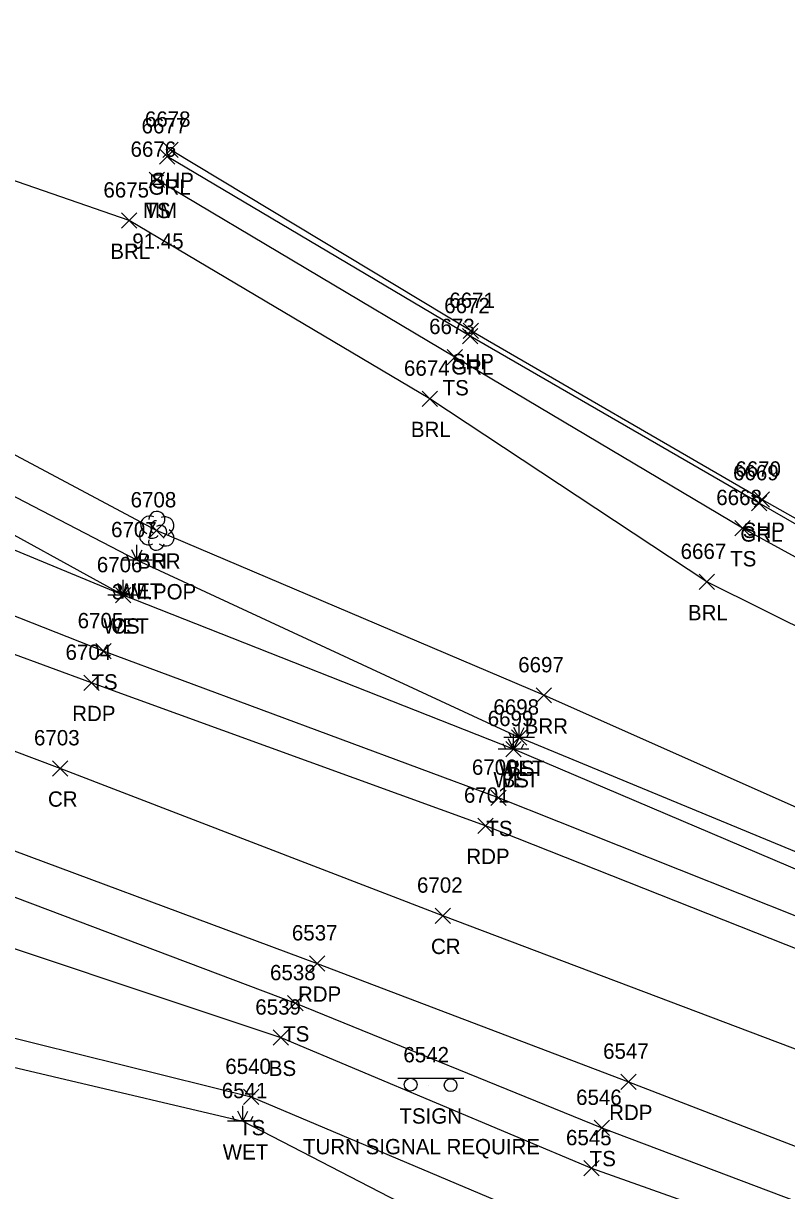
# Model space of a CAD drawing. Extents: x 1462089 to 1464015, y 730534 to 736144.
# Drawn here: x 1462817.1 to 1462916.7, y 731511.1 to 731663.4 of the extents above; entities that cross this region are included whole.
import ezdxf

# ---------------------------------------------------------------- set-up
doc = ezdxf.new("R2010")
doc.units = 0
for name, color, linetype in [('L_A', 7, 'Continuous'), ('L_C', 7, 'Continuous'), ('L_I', 7, 'Continuous'), ('L_TIC', 7, 'Continuous'), ('LABL', 7, 'Continuous'), ('LELB', 7, 'Continuous'), ('LTD', 7, 'Continuous'), ('LWET', 7, 'Continuous'), ('P_A', 7, 'Continuous'), ('P_I', 7, 'Continuous'), ('P_TIC', 7, 'Continuous'), ('PET', 7, 'Continuous'), ('PRC', 7, 'Continuous'), ('PSP', 7, 'Continuous'), ('R_A', 7, 'Continuous'), ('R_I', 7, 'Continuous'), ('R_TIC', 7, 'Continuous'), ('RGR', 7, 'Continuous'), ('S_A', 7, 'Continuous'), ('S_C', 7, 'Continuous'), ('S_I', 7, 'Continuous'), ('SRM', 7, 'Continuous'), ('SSGN', 7, 'Continuous')]:
    doc.layers.add(name, color=color, linetype=linetype)

msp = doc.modelspace()

# ---------------------------------------------------------------- linework, layer by layer
at = {"layer": 'L_TIC'}
for points in [[(1462833.53, 731641.96), (1462835.53, 731643.96)], [(1462835.53, 731641.96), (1462833.53, 731643.96)], [(1462829.94, 731636.64), (1462831.94, 731638.64)], [(1462831.94, 731636.64), (1462829.94, 731638.64)], [(1462872.41, 731618.83), (1462874.41, 731620.83)], [(1462874.41, 731618.83), (1462872.41, 731620.83)], [(1462869.14, 731613.39), (1462871.14, 731615.39)], [(1462871.14, 731613.39), (1462869.14, 731615.39)], [(1462833.51, 731596.22), (1462835.51, 731598.22)], [(1462835.51, 731596.22), (1462833.51, 731598.22)], [(1462909.91, 731596.52), (1462911.91, 731598.52)], [(1462911.91, 731596.52), (1462909.91, 731598.52)], [(1462905.26, 731589.49), (1462907.26, 731591.49)], [(1462907.26, 731589.49), (1462905.26, 731591.49)], [(1462829.16, 731587.75), (1462831.16, 731589.75)], [(1462831.16, 731587.75), (1462829.16, 731589.75)], [(1462826.61, 731580.45), (1462828.61, 731582.45)], [(1462828.61, 731580.45), (1462826.61, 731582.45)], [(1462884.04, 731574.7), (1462886.04, 731576.7)], [(1462886.04, 731574.7), (1462884.04, 731576.7)], [(1462880.79, 731569.18), (1462882.79, 731571.18)], [(1462882.79, 731569.18), (1462880.79, 731571.18)], [(1462880.06, 731567.69), (1462882.06, 731569.69)], [(1462882.06, 731567.69), (1462880.06, 731569.69)], [(1462878.11, 731561.33), (1462880.11, 731563.33)], [(1462880.11, 731561.33), (1462878.11, 731563.33)], [(1462851.61, 731534.53), (1462853.61, 731536.53)], [(1462853.61, 731534.53), (1462851.61, 731536.53)], [(1462849.71, 731530.04), (1462851.71, 731532.04)], [(1462851.71, 731530.04), (1462849.71, 731532.04)], [(1462845.87, 731522.3), (1462847.87, 731524.3)], [(1462847.87, 731522.3), (1462845.87, 731524.3)], [(1462891.59, 731518.26), (1462893.59, 731520.26)], [(1462893.59, 731518.26), (1462891.59, 731520.26)], [(1462890.22, 731513), (1462892.22, 731515)], [(1462892.22, 731513), (1462890.22, 731515)]]:
    msp.add_lwpolyline(points, dxfattribs=at)
at = {"layer": 'LABL'}
for points in [[(1463031.85, 731524.15), (1463024.22, 731515.5), (1462977.15, 731533.67), (1462930.95, 731555.28), (1462885.04, 731575.7), (1462834.51, 731597.22), (1462803.07, 731613.94), (1462803.87, 731628.84), (1462811.96, 731644.23)], [(1463031.85, 731524.15), (1462988.28, 731548.09), (1462943.29, 731572.1), (1462906.26, 731590.49), (1462870.14, 731614.39), (1462830.94, 731637.64), (1462811.96, 731644.23)]]:
    msp.add_lwpolyline(points, dxfattribs=at)
at = {"layer": 'LELB'}
for points in [[(1463119.6, 731469.74), (1463069.73, 731487.53), (1463021.46, 731507.93), (1462974.33, 731526.26), (1462926.32, 731543.54), (1462879.11, 731562.33), (1462827.61, 731581.45), (1462784.13, 731598.58), (1462763.62, 731605.93), (1462736.08, 731619.36), (1462729.89, 731630.52), (1462727.38, 731651.69), (1462726.82, 731663.37)], [(1462830.16, 731588.75), (1462785.28, 731607.33), (1462764.16, 731612.54), (1462740.16, 731624.2), (1462735.77, 731624.99), (1462735.73, 731638.84), (1462738.32, 731647.97)], [(1463216.41, 731432.84), (1463196.86, 731441.6), (1463172.22, 731454.72), (1463127.76, 731480.4), (1463076.47, 731505.5), (1463033.85, 731528.54), (1462991.5, 731551.77), (1462947.03, 731577.76), (1462910.91, 731597.52), (1462873.41, 731619.83), (1462834.53, 731642.96)], [(1462725.83, 731477.73), (1462699.03, 731484.88), (1462678.02, 731490.51), (1462672.21, 731492.87), (1462685.03, 731534.1), (1462694.09, 731551.02), (1462707.07, 731562.68), (1462723.7, 731570.83), (1462738.52, 731573.85), (1462757.84, 731571.09), (1462803.89, 731553.92), (1462852.61, 731535.53), (1462892.59, 731519.26), (1462943.53, 731500), (1462989.56, 731482.33), (1463038.41, 731464.73), (1463096.36, 731442.72), (1463144.39, 731425.15), (1463184.91, 731409.31), (1463228.27, 731391.66), (1463272.85, 731369.67), (1463317.31, 731351.5), (1463360.65, 731325.78), (1463401.48, 731298.99)], [(1463198.61, 731435.81), (1463172.21, 731447.97), (1463121.62, 731472.24), (1463071.4, 731492.14), (1463023.17, 731512.08), (1462976.42, 731531.07), (1462930.04, 731550.24), (1462881.79, 731570.18)], [(1463172.21, 731447.97), (1463119.6, 731469.74), (1463070.36, 731489.69), (1463021.92, 731509.58), (1462975.42, 731528.81), (1462928.9, 731548.31), (1462881.06, 731568.69)], [(1462704.46, 731497.81), (1462686.16, 731500.02), (1462698.22, 731528.94), (1462703.29, 731542), (1462714.64, 731556.34), (1462732.86, 731563.96), (1462758.79, 731560.72), (1462800.62, 731547.77), (1462850.71, 731531.04), (1462891.22, 731514), (1462941.79, 731496.05), (1462986.9, 731476.74), (1463039.19, 731460.33), (1463094.46, 731438.38), (1463142.72, 731421.22), (1463180.95, 731402.04), (1463225.03, 731385.65), (1463269.42, 731363.58), (1463313.96, 731345.04), (1463357.55, 731320.57), (1463397.02, 731291.85), (1463445.25, 731256.26)], [(1462729.89, 731554.83), (1462752.88, 731550.71), (1462796.34, 731535.84), (1462846.87, 731523.3), (1462891.6, 731504.38), (1462938.92, 731483.15), (1462981.55, 731463.36), (1463030.83, 731437.13), (1463081.03, 731412.21)]]:
    msp.add_lwpolyline(points, dxfattribs=at)
at = {"layer": 'LTD'}
msp.add_line((1462834.51, 731597.22), (1462834.51, 731597.22), dxfattribs=at)
msp.add_line((1462834.51, 731597.22), (1462834.51, 731597.22), dxfattribs=at)
msp.add_arc((1462834.56, 731598.65), 1.05, 335.5272, 180.9563, dxfattribs=at)
for centre, major_axis, ratio, start_param, end_param in [((1462833.72, 731597.89), (1.21, -0.51), 0.895232, 1.570796, 4.712389), ((1462834.3, 731597.68), (-0.208, -0.792), 0.645439, 3.141593, 6.283185), ((1462835.01, 731597.05), (-0.5, 0.667), 0.989748, 3.141593, 6.283185), ((1462835.55, 731597.8), (-1.14, -0.48), 0.949671, 1.570796, 4.712389), ((1462833.43, 731596.51), (0.58, -1.04), 0.959034, 3.141593, 6.283185), ((1462834.05, 731596.47), (-0.625, -0.083), 0.423636, 0, 3.141593), ((1462835.51, 731596.39), (-1.09, 0.79), 0.841452, 1.570796, 4.712389), ((1462834.51, 731595.72), (0.26, 1.06), 0.942809, 1.570796, 4.712389)]:
    msp.add_ellipse(centre, major_axis=major_axis, ratio=ratio, start_param=start_param, end_param=end_param, dxfattribs=at)
at = {"layer": 'LWET'}
for p, q in [((1462831.96, 731593.33), (1462831.96, 731595.33)), ((1462833.96, 731593.33), (1462829.96, 731593.33)), ((1462830.96, 731593.33), (1462830.63, 731594)), ((1462831.96, 731593.33), (1462831.3, 731594.67)), ((1462831.96, 731593.33), (1462832.63, 731594.67)), ((1462832.96, 731593.33), (1462833.3, 731594)), ((1462830.16, 731588.75), (1462830.16, 731590.75)), ((1462832.16, 731588.75), (1462828.16, 731588.75)), ((1462829.16, 731588.75), (1462828.82, 731589.42)), ((1462830.16, 731588.75), (1462829.49, 731590.08)), ((1462830.16, 731588.75), (1462830.82, 731590.08)), ((1462831.16, 731588.75), (1462831.49, 731589.42)), ((1462881.79, 731570.18), (1462881.79, 731572.18)), ((1462881.79, 731570.18), (1462881.79, 731572.18)), ((1462880.79, 731570.18), (1462880.46, 731570.84)), ((1462880.79, 731570.18), (1462880.46, 731570.84)), ((1462881.06, 731568.69), (1462881.06, 731570.69)), ((1462881.79, 731570.18), (1462881.12, 731571.51)), ((1462881.79, 731570.18), (1462881.12, 731571.51)), ((1462881.79, 731570.18), (1462882.46, 731571.51)), ((1462881.79, 731570.18), (1462882.46, 731571.51)), ((1462882.79, 731570.18), (1462883.12, 731570.84)), ((1462882.79, 731570.18), (1462883.12, 731570.84)), ((1462880.06, 731568.69), (1462879.73, 731569.36)), ((1462883.79, 731570.18), (1462879.79, 731570.18)), ((1462883.79, 731570.18), (1462879.79, 731570.18)), ((1462881.06, 731568.69), (1462880.4, 731570.03)), ((1462881.06, 731568.69), (1462881.73, 731570.03)), ((1462882.06, 731568.69), (1462882.4, 731569.36)), ((1462883.06, 731568.69), (1462879.06, 731568.69)), ((1462845.76, 731520.14), (1462845.76, 731522.14)), ((1462844.76, 731520.14), (1462844.43, 731520.81)), ((1462845.76, 731520.14), (1462845.09, 731521.47)), ((1462845.76, 731520.14), (1462846.43, 731521.47)), ((1462846.76, 731520.14), (1462847.09, 731520.81)), ((1462847.76, 731520.14), (1462843.76, 731520.14))]:
    msp.add_line(p, q, dxfattribs=at)
for points in [[(1462881.79, 731570.18), (1462881.06, 731568.69), (1462830.16, 731588.75), (1462789.68, 731611.04), (1462784.3, 731613.31), (1462766.07, 731617.11), (1462744.21, 731627.09), (1462743.62, 731628.48), (1462744.64, 731630.73)], [(1462881.79, 731570.18), (1462831.96, 731593.33), (1462790.37, 731614.89), (1462784.14, 731617.31), (1462766.81, 731621.51), (1462744.64, 731630.73)], [(1462733.57, 731494.55), (1462725.26, 731500.55), (1462719.94, 731502.96), (1462723.6, 731512.41), (1462733.75, 731518.35), (1462743.36, 731523.25), (1462753.89, 731528.6), (1462746.86, 731535.71), (1462735.45, 731540.19), (1462722.91, 731541.96), (1462719.94, 731549.27), (1462730.7, 731550.95), (1462750.36, 731546.11), (1462796.24, 731531.79), (1462845.76, 731520.14), (1462890.22, 731497.14), (1462935.58, 731479.91), (1462979.84, 731458.59), (1463028.53, 731430.07), (1463078.39, 731408.92), (1463133.15, 731393.57), (1463171.56, 731375.44), (1463214.42, 731357.49), (1463259.4, 731337.33)]]:
    msp.add_lwpolyline(points, dxfattribs=at)
at = {"layer": 'P_TIC'}
for points in [[(1462835.34, 731645.88), (1462837.34, 731647.88)], [(1462837.34, 731645.88), (1462835.34, 731647.88)], [(1462874.48, 731622.24), (1462876.48, 731624.24)], [(1462876.48, 731622.24), (1462874.48, 731624.24)], [(1462912.43, 731600.23), (1462914.43, 731602.23)], [(1462914.43, 731600.23), (1462912.43, 731602.23)], [(1462825.02, 731576.33), (1462827.02, 731578.33)], [(1462827.02, 731576.33), (1462825.02, 731578.33)], [(1462820.92, 731565.17), (1462822.92, 731567.17)], [(1462822.92, 731565.17), (1462820.92, 731567.17)], [(1462876.42, 731557.69), (1462878.42, 731559.69)], [(1462878.42, 731557.69), (1462876.42, 731559.69)], [(1462870.86, 731545.95), (1462872.86, 731547.95)], [(1462872.86, 731545.95), (1462870.86, 731547.95)], [(1462854.47, 731539.72), (1462856.47, 731541.72)], [(1462856.47, 731539.72), (1462854.47, 731541.72)], [(1462895.06, 731524.28), (1462897.06, 731526.28)], [(1462897.06, 731524.28), (1462895.06, 731526.28)]]:
    msp.add_lwpolyline(points, dxfattribs=at)
at = {"layer": 'PET'}
for points in [[(1463461.34, 731279.61), (1463416.02, 731311.33), (1463372.71, 731341.8), (1463324.96, 731373.71), (1463274.92, 731400.55), (1463226.84, 731425.24), (1463198.61, 731435.81), (1463171.74, 731446.45), (1463119.56, 731465.71), (1463068.75, 731485.01), (1463020.22, 731503.96), (1462972.87, 731521.72), (1462924.96, 731539.86), (1462877.42, 731558.69), (1462826.02, 731577.33), (1462782.49, 731593.34), (1462768.74, 731598.43), (1462762.18, 731600.75), (1462739.52, 731609.73), (1462723.72, 731618.83), (1462715.82, 731624.41), (1462713.48, 731627.53), (1462712.47, 731631.19), (1462712.89, 731635.26)], [(1462682, 731542.57), (1462690.37, 731554.44), (1462701.87, 731565.32), (1462718.63, 731575.1), (1462733.82, 731578.91), (1462746.81, 731578.39), (1462756.2, 731576.5), (1462761.65, 731574.84), (1462805.91, 731559.14), (1462855.47, 731540.72), (1462896.06, 731525.28), (1462946.06, 731505.97), (1462992.04, 731488.44), (1463040, 731470.15), (1463098.6, 731447.89), (1463146.47, 731429.53), (1463186.4, 731413.97), (1463230.08, 731397.45), (1463276.87, 731377.97), (1463320.08, 731356.26), (1463363.63, 731330.24), (1463405.12, 731302.86), (1463454, 731267.4)]]:
    msp.add_lwpolyline(points, dxfattribs=at)
at = {"layer": 'PRC'}
msp.add_lwpolyline([(1463372.71, 731341.8), (1463323.02, 731368.31), (1463272.12, 731392.66), (1463219.71, 731414.93), (1463167.62, 731434.61), (1463114.61, 731454.7), (1463064.71, 731473.62), (1463016.24, 731492.36), (1462967.74, 731510.88), (1462920.72, 731528.45), (1462871.86, 731546.95), (1462821.92, 731566.17), (1462781.52, 731581.37), (1462739.57, 731595.33), (1462703.33, 731606.12)], dxfattribs=at)
at = {"layer": 'PSP'}
msp.add_lwpolyline([(1463226.84, 731425.24), (1463216.41, 731432.84), (1463198.12, 731443.83), (1463173.9, 731457.95), (1463079.72, 731509.62), (1463036.91, 731532.72), (1462993.54, 731556.69), (1462949.22, 731581.05), (1462913.43, 731601.23), (1462875.48, 731623.24), (1462836.34, 731646.88)], dxfattribs=at)
at = {"layer": 'R_TIC'}
for points in [[(1462834.91, 731645.01), (1462836.91, 731647.01)], [(1462836.91, 731645.01), (1462834.91, 731647.01)], [(1462874.39, 731621.55), (1462876.39, 731623.55)], [(1462876.39, 731621.55), (1462874.39, 731623.55)], [(1462912.11, 731599.75), (1462914.11, 731601.75)], [(1462914.11, 731599.75), (1462912.11, 731601.75)]]:
    msp.add_lwpolyline(points, dxfattribs=at)
at = {"layer": 'RGR'}
msp.add_lwpolyline([(1463198.12, 731443.83), (1463173.45, 731457.19), (1463126.58, 731483.02), (1463079.48, 731508.97), (1463036.72, 731532.22), (1462993.15, 731555.95), (1462948.71, 731580.28), (1462913.11, 731600.75), (1462875.39, 731622.55), (1462835.91, 731646.01)], dxfattribs=at)
at = {"layer": 'SRM'}
msp.add_lwpolyline([(1462833.9, 731643.59), (1462835.15, 731643.59), (1462835.15, 731642.34), (1462833.9, 731642.34)], close=True, dxfattribs=at)
msp.add_circle((1462834.53, 731642.96), 0.0833, dxfattribs=at)
at = {"layer": 'SSGN'}
for p, q in [((1462865.99, 731525.74), (1462874.58, 731525.74)), ((1462870.01, 731524.84), (1462870.01, 731524.84))]:
    msp.add_line(p, q, dxfattribs=at)
for centre in [(1462867.65, 731524.91), (1462872.86, 731524.84)]:
    msp.add_circle(centre, 0.833, dxfattribs=at)

# ---------------------------------------------------------------- texts
at = {"layer": 'L_A'}
for s, p in [('TS', (1462832.94, 731637.96)), ('BRL', (1462828.48, 731632.64)), ('TS', (1462871.82, 731614.83)), ('BRL', (1462867.68, 731609.39)), ('BRR', (1462832, 731592.22)), ('H', (1462833.94, 731592.22)), ('TS', (1462909.32, 731592.52)), ('WET', (1462829.34, 731588.33)), ('BRL', (1462903.81, 731585.49)), ('WET', (1462827.54, 731583.75)), ('CS', (1462828.6, 731583.75)), ('TS', (1462826.02, 731576.45)), ('BRR', (1462882.52, 731570.7)), ('WET', (1462879.17, 731565.18)), ('WET', (1462879.17, 731565.18)), ('BS', (1462880.23, 731565.18)), ('WET', (1462878.44, 731563.69)), ('BS', (1462879.51, 731563.69)), ('TS', (1462877.52, 731557.33)), ('TS', (1462851.02, 731530.53)), ('BS', (1462849.15, 731526.04)), ('TS', (1462845.28, 731518.3)), ('WET', (1462843.14, 731515.14)), ('TS', (1462891, 731514.26))]:
    msp.add_text(s, height=2, dxfattribs=at).set_placement(p)
at = {"layer": 'L_C'}
msp.add_text('3-M.POP', height=2, dxfattribs=at).set_placement((1462828.69, 731588.22))
at = {"layer": 'L_I'}
for s, p in [('6676', (1462831.12, 731645.96)), ('6675', (1462827.58, 731640.64)), ('6673', (1462870.06, 731622.83)), ('6674', (1462866.78, 731617.39)), ('6668', (1462907.51, 731600.52)), ('6708', (1462831.13, 731600.22)), ('6708', (1462831.13, 731600.22)), ('6707', (1462828.58, 731596.33)), ('6667', (1462902.86, 731593.49)), ('6706', (1462826.72, 731591.75)), ('6706', (1462826.72, 731591.75)), ('6705', (1462824.22, 731584.45)), ('6697', (1462881.68, 731578.7)), ('6698', (1462878.44, 731573.18)), ('6698', (1462878.44, 731573.18)), ('6698', (1462878.44, 731573.18)), ('6699', (1462877.7, 731571.69)), ('6699', (1462877.7, 731571.69)), ('6700', (1462875.64, 731565.33)), ('6538', (1462849.31, 731538.53)), ('6539', (1462847.39, 731534.04)), ('6540', (1462843.48, 731526.3)), ('6541', (1462843.02, 731523.14)), ('6546', (1462889.23, 731522.26)), ('6545', (1462887.91, 731517))]:
    msp.add_text(s, height=2, dxfattribs=at).set_placement(p)
at = {"layer": 'P_A'}
for s, p in [('SHP', (1462833.88, 731641.88)), ('SHP', (1462873.01, 731618.24)), ('SHP', (1462910.96, 731596.23)), ('RDP', (1462823.51, 731572.33)), ('CR', (1462820.35, 731561.17)), ('RDP', (1462874.91, 731553.69)), ('CR', (1462870.3, 731541.95)), ('RDP', (1462852.95, 731535.72)), ('RDP', (1462893.54, 731520.28))]:
    msp.add_text(s, height=2, dxfattribs=at).set_placement(p)
at = {"layer": 'P_I'}
for s, p in [('6678', (1462832.99, 731649.88)), ('6671', (1462872.69, 731626.24)), ('6670', (1462909.99, 731604.23)), ('6704', (1462822.64, 731580.33)), ('6703', (1462818.53, 731569.17)), ('6701', (1462874.6, 731561.69)), ('6702', (1462868.48, 731549.95)), ('6537', (1462852.16, 731543.72)), ('6547', (1462892.75, 731528.28))]:
    msp.add_text(s, height=2, dxfattribs=at).set_placement(p)
at = {"layer": 'R_A'}
for p in [(1462833.46, 731641.01), (1462872.93, 731617.55), (1462910.65, 731595.75)]:
    msp.add_text('GRL', height=2, dxfattribs=at).set_placement(p)
at = {"layer": 'R_I'}
for s, p in [('6677', (1462832.56, 731649.01)), ('6672', (1462872.03, 731625.55)), ('6669', (1462909.7, 731603.75))]:
    msp.add_text(s, height=2, dxfattribs=at).set_placement(p)
at = {"layer": 'S_A'}
for s, p in [('MM', (1462832.72, 731637.96)), ('TSIGN', (1462866.18, 731519.82))]:
    msp.add_text(s, height=2, dxfattribs=at).set_placement(p)
at = {"layer": 'S_C'}
for s, p in [('91.45', (1462831.35, 731633.96)), ('TURN SIGNAL REQUIRE', (1462853.61, 731515.82))]:
    msp.add_text(s, height=2, dxfattribs=at).set_placement(p)
at = {"layer": 'S_I'}
for s, p in [('6676', (1462831.12, 731645.96)), ('6542', (1462866.7, 731527.82))]:
    msp.add_text(s, height=2, dxfattribs=at).set_placement(p)

doc.saveas('drawing.dxf')
